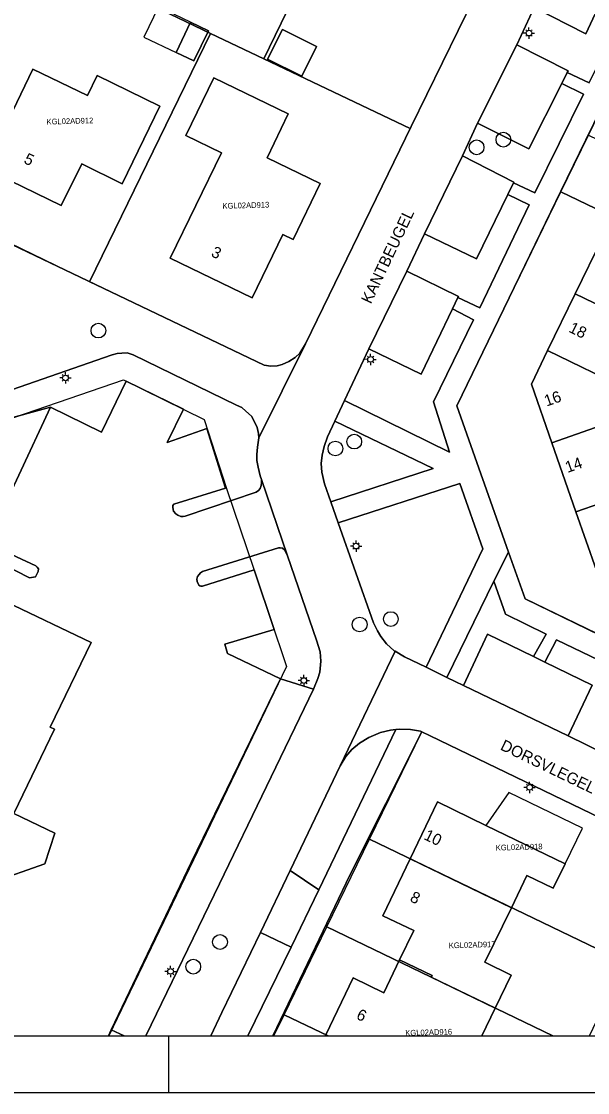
# Model space of a CAD drawing. Extents: x 124901 to 125496, y 515369 to 515789.
# Drawn here: x 125378 to 125427.9, y 515368.5 to 515463 of the extents above; entities that cross this region are included whole.
import ezdxf

# ---------------------------------------------------------------- set-up
doc = ezdxf.new("R2010")
doc.units = 0
for name, color, linetype in [('Alg Kaders', 7, 'Continuous'), ('Gebouw', 7, 'Continuous'), ('Inrit', 7, 'Continuous'), ('Lichtmast', 7, 'Continuous'), ('Luifel', 7, 'Continuous'), ('Onbegroeid terrein', 7, 'Continuous'), ('Parkeren', 7, 'Continuous'), ('Perceelnummers', 7, 'Continuous'), ('Perceelsgrenzen', 7, 'Continuous'), ('Putten', 7, 'Continuous'), ('Teksten', 7, 'Continuous'), ('Vegetatie', 7, 'Continuous'), ('Voetpad', 7, 'Continuous'), ('Wegen lokale weg', 7, 'Continuous')]:
    doc.layers.add(name, color=color, linetype=linetype)

msp = doc.modelspace()

# ---------------------------------------------------------------- linework, layer by layer
at = {"layer": 'Alg Kaders'}
msp.add_line((125390.924, 515373.543), (125390.926, 515368.543), dxfattribs=at)
for points in [[(125495.925, 515789.043), (124901.425, 515789.043), (124901.425, 515368.543), (125495.925, 515368.543)], [(125490.925, 515784.043), (124906.425, 515784.043), (124906.425, 515373.543), (125490.925, 515373.543)]]:
    msp.add_lwpolyline(points, close=True, dxfattribs=at)
at = {"layer": 'Gebouw'}
for points in [[(125391.586, 515460.272), (125393.165, 515459.518), (125394.441, 515462.189), (125392.862, 515462.943)], [(125400.963, 515462.304), (125399.651, 515459.678), (125402.66, 515458.174), (125403.972, 515460.801)], [(125384.62, 515458.25), (125383.768, 515456.476), (125378.95, 515458.79), (125374.731, 515450.024), (125381.47, 515446.78), (125383.268, 515450.44), (125386.83, 515448.69), (125390.16, 515455.54)], [(125398.293, 515438.629), (125400.999, 515444.211), (125401.898, 515443.775), (125404.29, 515448.71), (125399.606, 515450.977), (125401.48, 515454.85), (125394.91, 515458.03), (125392.448, 515452.952), (125395.585, 515451.431), (125391.076, 515442.128)], [(125429.2, 515443.99), (125426.768, 515438.975), (125434.939, 515435.036), (125437.359, 515440.057)], [(125431.364, 515430.569), (125432.54, 515430.06), (125434.939, 515435.036), (125426.768, 515438.975), (125424.342, 515433.974)], [(125431.364, 515430.569), (125424.342, 515433.974), (125422.91, 515431.02), (125424.711, 515425.853), (125431.246, 515428.13), (125430.757, 515429.488)], [(125431.246, 515428.13), (125424.711, 515425.853), (125426.84, 515419.745), (125433.44, 515422.046)], [(125431.621, 515413.142), (125435.027, 515420.2), (125433.911, 515420.74), (125433.44, 515422.046), (125426.84, 515419.745), (125428.64, 515414.58)], [(125414.63, 515394.17), (125412.224, 515389.156), (125421.143, 515384.841), (125422.519, 515387.686), (125424.837, 515386.564), (125425.88, 515388.72), (125418.886, 515392.108)], [(125412.224, 515389.156), (125409.817, 515384.142), (125412.537, 515382.837), (125411.288, 515380.235), (125414.154, 515378.859), (125414.086, 515378.718), (125419.721, 515375.991), (125421.134, 515378.911), (125418.816, 515380.032), (125421.143, 515384.841)]]:
    msp.add_lwpolyline(points, close=True, dxfattribs=at)
for points in [[(125372.005, 515373.543), (125369.392, 515381.106), (125374.299, 515382.802), (125374.757, 515381.475), (125375.06, 515381.58), (125374.601, 515382.911), (125376.54, 515383.58), (125375.324, 515387.078), (125380.02, 515388.71), (125380.89, 515391.42), (125377.294, 515393.154), (125380.88, 515400.59), (125380.493, 515400.777), (125384.09, 515408.22), (125376.623, 515411.811), (125376.81, 515412.2), (125374.711, 515413.213), (125369.39, 515415.78)], [(125418.537, 515373.543), (125419.721, 515375.991), (125414.086, 515378.718), (125414.154, 515378.859), (125411.288, 515380.235), (125409.903, 515377.35), (125407.184, 515378.655), (125404.78, 515373.646), (125404.992, 515373.543)], [(125404.992, 515373.543), (125404.78, 515373.646), (125404.731, 515373.543)]]:
    msp.add_lwpolyline(points, dxfattribs=at)
at = {"layer": 'Inrit'}
msp.add_lwpolyline([(125401.746, 515381.372), (125404.163, 515386.414), (125401.637, 515388.136), (125399.022, 515382.67)], close=True, dxfattribs=at)
at = {"layer": 'Lichtmast'}
for p, q in [((125422.396, 515461.981), (125422.196, 515461.98)), ((125422.484, 515462.192), (125422.414, 515462.263)), ((125422.696, 515462.28), (125422.696, 515462.48)), ((125422.908, 515462.192), (125422.979, 515462.264)), ((125422.996, 515461.98), (125423.196, 515461.98)), ((125422.484, 515461.768), (125422.412, 515461.697)), ((125422.696, 515461.68), (125422.696, 515461.48)), ((125422.908, 515461.768), (125422.978, 515461.697)), ((125408.52, 515433.418), (125408.45, 515433.489)), ((125408.732, 515433.506), (125408.732, 515433.706)), ((125408.944, 515433.418), (125409.015, 515433.49)), ((125408.432, 515433.207), (125408.232, 515433.206)), ((125408.52, 515432.994), (125408.448, 515432.923)), ((125408.732, 515432.906), (125408.732, 515432.706)), ((125408.944, 515432.994), (125409.014, 515432.923)), ((125409.032, 515433.206), (125409.232, 515433.206)), ((125381.622, 515431.776), (125381.552, 515431.847)), ((125381.834, 515431.864), (125381.834, 515432.064)), ((125382.046, 515431.776), (125382.117, 515431.848)), ((125381.534, 515431.565), (125381.334, 515431.564)), ((125381.622, 515431.352), (125381.55, 515431.281)), ((125381.834, 515431.264), (125381.834, 515431.064)), ((125382.046, 515431.352), (125382.116, 515431.281)), ((125382.134, 515431.564), (125382.334, 515431.564)), ((125407.157, 515416.737), (125406.957, 515416.736)), ((125407.245, 515416.524), (125407.173, 515416.453)), ((125407.245, 515416.948), (125407.175, 515417.019)), ((125407.457, 515417.036), (125407.457, 515417.236)), ((125407.669, 515416.948), (125407.74, 515417.02)), ((125407.669, 515416.524), (125407.739, 515416.453)), ((125407.757, 515416.736), (125407.957, 515416.736)), ((125407.457, 515416.436), (125407.457, 515416.236)), ((125402.632, 515405.09), (125402.562, 515405.161)), ((125402.844, 515405.178), (125402.844, 515405.378)), ((125403.056, 515405.09), (125403.127, 515405.162)), ((125402.544, 515404.879), (125402.344, 515404.878)), ((125402.632, 515404.666), (125402.56, 515404.595)), ((125402.844, 515404.578), (125402.844, 515404.378)), ((125403.056, 515404.666), (125403.126, 515404.595)), ((125403.144, 515404.878), (125403.344, 515404.878)), ((125422.544, 515395.671), (125422.474, 515395.742)), ((125422.756, 515395.759), (125422.756, 515395.959)), ((125422.968, 515395.671), (125423.039, 515395.743)), ((125422.456, 515395.46), (125422.256, 515395.459)), ((125422.544, 515395.247), (125422.472, 515395.176)), ((125422.756, 515395.159), (125422.756, 515394.959)), ((125422.968, 515395.247), (125423.038, 515395.176)), ((125423.056, 515395.459), (125423.256, 515395.459)), ((125391.1, 515379.532), (125391.1, 515379.732)), ((125390.8, 515379.233), (125390.6, 515379.232)), ((125390.888, 515379.02), (125390.816, 515378.949)), ((125390.888, 515379.444), (125390.818, 515379.515)), ((125391.1, 515378.932), (125391.1, 515378.732)), ((125391.312, 515379.444), (125391.383, 515379.516)), ((125391.312, 515379.02), (125391.382, 515378.949)), ((125391.4, 515379.232), (125391.6, 515379.232))]:
    msp.add_line(p, q, dxfattribs=at)
for centre in [(125422.696, 515461.98), (125408.732, 515433.206), (125381.834, 515431.564), (125407.457, 515416.736), (125402.844, 515404.878), (125422.756, 515395.459), (125391.1, 515379.232)]:
    msp.add_circle(centre, 0.25, dxfattribs=at)
at = {"layer": 'Luifel'}
for points in [[(125390.035, 515464.294), (125388.759, 515461.623), (125391.586, 515460.272), (125392.862, 515462.943)], [(125420.917, 515395.015), (125418.886, 515392.108), (125425.88, 515388.72), (125427.406, 515391.871)]]:
    msp.add_lwpolyline(points, close=True, dxfattribs=at)
at = {"layer": 'Onbegroeid terrein'}
for points in [[(125369.078, 515447.143), (125383.134, 515440.443), (125399.357, 515432.703), (125399.947, 515432.603), (125400.496, 515432.629), (125400.953, 515432.76), (125401.514, 515433.006), (125402.096, 515433.374), (125402.495, 515433.741), (125402.993, 515434.569), (125411.309, 515451.669), (125412.318, 515453.738), (125423.349, 515476.349), (125375.06, 515499.729)], [(125436.24, 515470.006), (125427.701, 515452.562), (125425.513, 515448.05), (125424.626, 515446.221), (125416.323, 515429.095), (125420.891, 515416.201), (125422.352, 515412.077), (125435.475, 515405.706)], [(125428.64, 515414.58), (125426.84, 515419.745), (125424.711, 515425.853), (125422.91, 515431.02), (125424.342, 515433.974), (125426.768, 515438.975), (125429.2, 515443.99)], [(125369.957, 515418.385), (125378.674, 515413.948), (125379.191, 515414.037), (125379.294, 515414.205), (125379.44, 515414.497), (125379.45, 515414.718), (125379.352, 515414.885), (125379.218, 515414.988), (125374.915, 515417.009), (125380.523, 515428.985), (125376.433, 515427.864)], [(125455.601, 515373.543), (125456.426, 515375.251), (125456.94, 515376.246), (125457.099, 515377.21), (125457.169, 515377.67), (125457.051, 515378.227), (125456.737, 515378.751), (125456.326, 515379.227), (125440.731, 515387.103), (125413.999, 515400.01), (125413.253, 515400.357), (125406.947, 515387.767), (125400.118, 515373.543)], [(125404.731, 515373.543), (125404.78, 515373.646), (125407.184, 515378.655), (125409.903, 515377.35), (125411.288, 515380.235), (125412.537, 515382.837), (125409.817, 515384.142), (125412.224, 515389.156), (125414.63, 515394.17), (125418.886, 515392.108), (125425.88, 515388.72), (125424.837, 515386.564), (125422.519, 515387.686), (125421.143, 515384.841), (125418.816, 515380.032), (125421.134, 515378.911), (125419.721, 515375.991), (125418.537, 515373.543)]]:
    msp.add_lwpolyline(points, dxfattribs=at)
for points in [[(125393.165, 515459.518), (125391.586, 515460.272), (125392.862, 515462.943), (125394.441, 515462.189)], [(125400.963, 515462.304), (125403.972, 515460.801), (125402.66, 515458.174), (125399.651, 515459.678)], [(125383.768, 515456.476), (125384.62, 515458.25), (125390.16, 515455.54), (125386.83, 515448.69), (125383.268, 515450.44), (125381.47, 515446.78), (125374.731, 515450.024), (125378.95, 515458.79)], [(125400.999, 515444.211), (125398.293, 515438.629), (125391.076, 515442.128), (125395.585, 515451.431), (125392.448, 515452.952), (125394.91, 515458.03), (125401.48, 515454.85), (125399.606, 515450.977), (125404.29, 515448.71), (125401.898, 515443.775)]]:
    msp.add_lwpolyline(points, close=True, dxfattribs=at)
at = {"layer": 'Parkeren'}
for points in [[(125430.901, 515468.821), (125426.393, 515471.074), (125423.161, 515464.229), (125427.7, 515461.925), (125430.399, 515467.739)], [(125425.582, 515457.541), (125426.06, 515458.488), (125426.14, 515458.647), (125421.631, 515460.932), (125418.166, 515454.044), (125422.673, 515451.779)], [(125413.485, 515444.285), (125418.062, 515442.058), (125420.827, 515447.752), (125421.319, 515448.766), (125421.355, 515448.839), (125416.83, 515451.144)], [(125416.434, 515438.648), (125416.484, 515438.751), (125411.918, 515440.973), (125408.592, 515434.124), (125413.18, 515431.909), (125415.962, 515437.669)], [(125426.147, 515400), (125428.263, 515404.477), (125424.088, 515406.504), (125423.096, 515406.986), (125419.029, 515408.959), (125416.917, 515404.45)]]:
    msp.add_lwpolyline(points, close=True, dxfattribs=at)
for points in [[(125385.618, 515373.543), (125385.878, 515374.087), (125392.925, 515388.832), (125400.783, 515405.027), (125396.109, 515407.269), (125395.894, 515408.083), (125400.241, 515409.387), (125398.458, 515414.653), (125393.917, 515413.214), (125393.758, 515413.21), (125393.672, 515413.233), (125393.592, 515413.292), (125393.435, 515413.601), (125393.408, 515413.834), (125393.463, 515414.057), (125393.614, 515414.227), (125393.741, 515414.382), (125393.905, 515414.501), (125400.603, 515416.584), (125400.754, 515416.57), (125400.981, 515416.544), (125401.186, 515416.391), (125401.421, 515415.89), (125399.132, 515422.604), (125399.12, 515422.305), (125399.088, 515422.071), (125398.989, 515421.829), (125398.863, 515421.638), (125398.651, 515421.488), (125392.398, 515419.377), (125392.212, 515419.341), (125392.001, 515419.355), (125391.742, 515419.462), (125391.567, 515419.58), (125391.367, 515419.808), (125391.305, 515420.13), (125391.305, 515420.31), (125391.395, 515420.436), (125395.958, 515421.837), (125394.288, 515427.106), (125390.812, 515425.885), (125392.249, 515428.807), (125387.195, 515431.286), (125385.023, 515426.793), (125380.523, 515428.985), (125374.915, 515417.009), (125379.218, 515414.988), (125379.352, 515414.885), (125379.45, 515414.718), (125379.44, 515414.497), (125379.294, 515414.205), (125379.191, 515414.037), (125378.674, 515413.948), (125369.957, 515418.385)], [(125376.623, 515411.811), (125384.09, 515408.22), (125380.493, 515400.777), (125380.88, 515400.59), (125377.294, 515393.154), (125380.89, 515391.42), (125380.02, 515388.71), (125375.324, 515387.078)]]:
    msp.add_lwpolyline(points, dxfattribs=at)
at = {"layer": 'Perceelsgrenzen'}
for points in [[(125375.06, 515499.729), (125385.193, 515494.823), (125397.791, 515488.723), (125410.427, 515482.605), (125423.349, 515476.349), (125412.23, 515453.557), (125411.309, 515451.669), (125402.993, 515434.569), (125402.495, 515433.741), (125402.096, 515433.374), (125401.514, 515433.006), (125400.953, 515432.76), (125400.496, 515432.629), (125399.947, 515432.603), (125399.357, 515432.703), (125383.955, 515440.045), (125372.915, 515445.397)], [(125347.273, 515373.543), (125347.035, 515373.992), (125346.605, 515374.956), (125346.243, 515375.947), (125345.95, 515376.96), (125337.56, 515398.86), (125339.28, 515400.59), (125345.594, 515417.203), (125386.949, 515431.401), (125394.052, 515427.9), (125396.029, 515421.819), (125398.444, 515414.714), (125401.327, 515406.13), (125385.649, 515373.543)], [(125345.594, 515417.203), (125386.949, 515431.401), (125394.052, 515427.9), (125396.029, 515421.819), (125398.444, 515414.714), (125401.327, 515406.13), (125385.649, 515373.543)], [(125400.202, 515373.543), (125401.109, 515375.407), (125404.88, 515383.155), (125408.641, 515390.882), (125413.253, 515400.357), (125413.999, 515400.01), (125435.675, 515389.544), (125440.731, 515387.103), (125456.326, 515379.227), (125456.737, 515378.751), (125457.051, 515378.227), (125457.169, 515377.67), (125457.099, 515377.21), (125456.94, 515376.246), (125456.426, 515375.251), (125455.601, 515373.543)], [(125424.786, 515373.543), (125404.88, 515383.155), (125408.641, 515390.882), (125431.133, 515380.048), (125428.337, 515374.2), (125428.285, 515374.092), (125428.015, 515373.543)], [(125404.984, 515373.543), (125401.109, 515375.407), (125404.88, 515383.155), (125424.786, 515373.543)], [(125400.202, 515373.543), (125401.109, 515375.407), (125404.984, 515373.543)]]:
    msp.add_lwpolyline(points, dxfattribs=at)
for points in [[(125394.62, 515461.95), (125386.705, 515465.759), (125397.791, 515488.723), (125410.427, 515482.605), (125399.333, 515459.704)], [(125410.427, 515482.605), (125423.349, 515476.349), (125412.23, 515453.557), (125399.333, 515459.704)], [(125394.62, 515461.95), (125383.955, 515440.045), (125372.915, 515445.397), (125370.542, 515452.147), (125370.68, 515452.487), (125378.816, 515469.556), (125386.705, 515465.759)], [(125422.352, 515412.077), (125416.323, 515429.095), (125425.515, 515447.977), (125427.947, 515452.971), (125430.307, 515457.819), (125432.68, 515462.693), (125436.24, 515470.006), (125458.379, 515459.386), (125466.196, 515455.636), (125473.945, 515451.919), (125481.696, 515448.201), (125490.418, 515444.017), (125486.87, 515436.73), (125484.12, 515431.04), (125477.96, 515418.22), (125473.069, 515420.579), (125472.365, 515419.12), (125460.158, 515393.807), (125453.949, 515396.807)], [(125394.62, 515461.95), (125399.333, 515459.704), (125412.23, 515453.557), (125411.309, 515451.669), (125402.993, 515434.569), (125402.495, 515433.741), (125402.096, 515433.374), (125401.514, 515433.006), (125400.953, 515432.76), (125400.496, 515432.629), (125399.947, 515432.603), (125399.357, 515432.703), (125383.955, 515440.045)], [(125425.515, 515447.977), (125427.947, 515452.971), (125450.152, 515442.29), (125447.75, 515437.274), (125430.08, 515445.77)], [(125453.949, 515396.807), (125422.352, 515412.077), (125416.323, 515429.095), (125425.515, 515447.977), (125430.08, 515445.77), (125447.75, 515437.274), (125449.679, 515436.346), (125447.917, 515432.714), (125453.762, 515429.894), (125461.501, 515426.16), (125469.259, 515422.417), (125473.069, 515420.579), (125472.365, 515419.12), (125466.225, 515422.082), (125465.264, 515420.091), (125461.584, 515412.672), (125460.064, 515409.52)], [(125431.133, 515380.048), (125408.641, 515390.882), (125413.253, 515400.357), (125413.999, 515400.01), (125435.675, 515389.544)]]:
    msp.add_lwpolyline(points, close=True, dxfattribs=at)
at = {"layer": 'Putten'}
for centre in [(125418.08, 515451.9), (125420.44, 515452.58), (125384.74, 515435.74), (125405.63, 515425.34), (125407.29, 515425.95), (125410.52, 515410.3), (125407.77, 515409.82), (125395.46, 515381.82), (125393.1, 515379.65)]:
    msp.add_circle(centre, 0.65, dxfattribs=at)
at = {"layer": 'Vegetatie'}
for points in [[(125421.631, 515460.932), (125426.14, 515458.647), (125426.06, 515458.488), (125428.014, 515457.588), (125432.457, 515466.767), (125430.399, 515467.739), (125427.7, 515461.925), (125423.161, 515464.229)], [(125425.582, 515457.541), (125422.673, 515451.779), (125418.166, 515454.044), (125416.83, 515451.144), (125421.355, 515448.839), (125421.319, 515448.766), (125423.219, 515447.878), (125427.49, 515456.592)], [(125420.827, 515447.752), (125418.062, 515442.058), (125413.485, 515444.285), (125411.918, 515440.973), (125416.484, 515438.751), (125416.434, 515438.648), (125418.36, 515437.737), (125422.705, 515446.846)], [(125415.962, 515437.669), (125413.18, 515431.909), (125408.592, 515434.124), (125406.432, 515429.562), (125415.691, 515425.014), (125414.289, 515429.452), (125417.805, 515436.694)], [(125404.628, 515425.529), (125404.453, 515424.746), (125404.384, 515424.022), (125404.436, 515423.262), (125404.66, 515422.237), (125405.221, 515420.648), (125414.265, 515423.583), (125405.575, 515427.751), (125404.926, 515426.381)], [(125410.89, 515407.472), (125411.714, 515406.97), (125413.621, 515406.046), (125418.625, 515416.487), (125416.601, 515422.265), (125405.875, 515418.797), (125408.998, 515409.957), (125409.353, 515409.254), (125409.624, 515408.777), (125410.144, 515408.114), (125410.82, 515407.514)], [(125400.783, 515405.027), (125403.713, 515404.119), (125404.079, 515405.064), (125404.253, 515405.631), (125404.34, 515406.575), (125404.28, 515407.423), (125403.978, 515408.446), (125401.421, 515415.89), (125401.186, 515416.391), (125400.981, 515416.544), (125400.754, 515416.57), (125400.603, 515416.584), (125393.905, 515414.501), (125393.741, 515414.382), (125393.614, 515414.227), (125393.463, 515414.057), (125393.408, 515413.834), (125393.435, 515413.601), (125393.592, 515413.292), (125393.672, 515413.233), (125393.758, 515413.21), (125393.917, 515413.214), (125398.458, 515414.653), (125400.241, 515409.387), (125395.894, 515408.083), (125396.109, 515407.269)], [(125419.029, 515408.959), (125423.096, 515406.986), (125424.199, 515408.973), (125420.617, 515410.742), (125419.603, 515413.638), (125415.465, 515405.153), (125416.917, 515404.45)], [(125428.263, 515404.477), (125426.147, 515400), (125431.103, 515397.551), (125433.34, 515402.034), (125437.38, 515400.095), (125438.393, 515402.078), (125425.11, 515408.481), (125424.088, 515406.504)], [(125407.072, 515398.8), (125406.548, 515398.168), (125406.048, 515397.354), (125401.637, 515388.136), (125404.163, 515386.414), (125410.945, 515400.557), (125410.484, 515400.502), (125409.616, 515400.303), (125408.567, 515399.848), (125407.742, 515399.356)]]:
    msp.add_lwpolyline(points, close=True, dxfattribs=at)
for points in [[(125376.433, 515427.864), (125380.523, 515428.985), (125385.023, 515426.793), (125387.195, 515431.286), (125392.249, 515428.807), (125390.812, 515425.885), (125394.288, 515427.106), (125395.958, 515421.837), (125391.395, 515420.436), (125391.305, 515420.31), (125391.305, 515420.13), (125391.367, 515419.808), (125391.567, 515419.58), (125391.742, 515419.462), (125392.001, 515419.355), (125392.212, 515419.341), (125392.398, 515419.377), (125398.651, 515421.488), (125398.863, 515421.638), (125398.989, 515421.829), (125399.088, 515422.071), (125399.12, 515422.305), (125399.132, 515422.604), (125399.012, 515422.941), (125398.812, 515423.705), (125398.711, 515424.294), (125398.702, 515424.828), (125398.766, 515425.453), (125398.882, 515426.281), (125398.849, 515426.667), (125398.729, 515427.184), (125398.537, 515427.642), (125398.223, 515428.181), (125397.751, 515428.65), (125397.373, 515428.945), (125396.919, 515429.164), (125387.816, 515433.589), (125387.261, 515433.791), (125386.8, 515433.752), (125386.398, 515433.725), (125385.959, 515433.617), (125375.706, 515430.042)], [(125388.934, 515373.543), (125395.406, 515386.94), (125403.713, 515404.119), (125400.783, 515405.027), (125392.925, 515388.832), (125385.878, 515374.087), (125387.016, 515373.543)], [(125397.907, 515373.543), (125401.746, 515381.372), (125399.022, 515382.67), (125395.635, 515375.592), (125394.645, 515373.543)], [(125387.016, 515373.543), (125385.878, 515374.087), (125385.618, 515373.543)]]:
    msp.add_lwpolyline(points, dxfattribs=at)
at = {"layer": 'Voetpad'}
for points in [[(125428.014, 515457.588), (125426.06, 515458.488), (125425.582, 515457.541), (125427.49, 515456.592), (125423.219, 515447.878), (125421.319, 515448.766), (125420.827, 515447.752), (125422.705, 515446.846), (125418.36, 515437.737), (125416.434, 515438.648), (125415.962, 515437.669), (125417.805, 515436.694), (125414.289, 515429.452), (125415.691, 515425.014), (125406.432, 515429.562), (125405.575, 515427.751), (125414.265, 515423.583), (125405.221, 515420.648), (125405.875, 515418.797), (125416.601, 515422.265), (125418.625, 515416.487), (125413.621, 515406.046), (125415.465, 515405.153), (125419.603, 515413.638), (125420.891, 515416.201), (125416.323, 515429.095), (125424.626, 515446.221), (125425.513, 515448.05), (125427.701, 515452.562), (125436.24, 515470.006)], [(125490.925, 515378.871), (125489.543, 515379.54), (125466.673, 515390.606), (125463.328, 515392.279), (125460.158, 515393.807), (125435.475, 515405.706), (125422.352, 515412.077), (125420.891, 515416.201), (125419.603, 515413.638), (125420.617, 515410.742), (125424.199, 515408.973), (125423.096, 515406.986), (125424.088, 515406.504), (125425.11, 515408.481), (125438.393, 515402.078), (125437.38, 515400.095), (125438.387, 515399.612), (125439.394, 515401.581), (125452.728, 515395.141), (125451.71, 515393.183), (125452.759, 515392.672), (125453.821, 515394.656), (125460.797, 515391.27), (125490.925, 515376.662)], [(125400.118, 515373.543), (125406.947, 515387.767), (125413.253, 515400.357), (125413.127, 515400.415), (125412.25, 515400.551), (125411.31, 515400.6), (125410.945, 515400.557), (125404.163, 515386.414), (125401.746, 515381.372), (125397.907, 515373.543)]]:
    msp.add_lwpolyline(points, dxfattribs=at)
at = {"layer": 'Wegen lokale weg'}
for points in [[(125423.349, 515476.349), (125412.318, 515453.738), (125411.309, 515451.669), (125402.993, 515434.569), (125398.882, 515426.281), (125398.766, 515425.453), (125398.702, 515424.828), (125398.711, 515424.294), (125398.812, 515423.705), (125399.012, 515422.941), (125399.132, 515422.604), (125401.421, 515415.89), (125403.978, 515408.446), (125404.28, 515407.423), (125404.34, 515406.575), (125404.253, 515405.631), (125404.079, 515405.064), (125403.713, 515404.119), (125395.406, 515386.94), (125388.934, 515373.543)], [(125394.645, 515373.543), (125395.635, 515375.592), (125399.022, 515382.67), (125401.637, 515388.136), (125406.048, 515397.354), (125410.89, 515407.472), (125410.82, 515407.514), (125410.144, 515408.114), (125409.624, 515408.777), (125409.353, 515409.254), (125408.998, 515409.957), (125405.875, 515418.797), (125405.221, 515420.648), (125404.66, 515422.237), (125404.436, 515423.262), (125404.384, 515424.022), (125404.453, 515424.746), (125404.628, 515425.529), (125404.926, 515426.381), (125405.575, 515427.751), (125406.432, 515429.562), (125408.592, 515434.124), (125411.918, 515440.973), (125413.485, 515444.285), (125416.83, 515451.144), (125418.166, 515454.044), (125421.631, 515460.932), (125423.161, 515464.229)], [(125375.706, 515430.042), (125385.959, 515433.617), (125386.398, 515433.725), (125386.8, 515433.752), (125387.261, 515433.791), (125387.816, 515433.589), (125396.919, 515429.164), (125397.373, 515428.945), (125397.751, 515428.65), (125398.223, 515428.181), (125398.537, 515427.642), (125398.729, 515427.184), (125398.849, 515426.667), (125398.882, 515426.281), (125402.993, 515434.569), (125402.495, 515433.741), (125402.096, 515433.374), (125401.514, 515433.006), (125400.953, 515432.76), (125400.496, 515432.629), (125399.947, 515432.603), (125399.357, 515432.703), (125383.134, 515440.443), (125369.078, 515447.143)], [(125431.103, 515397.551), (125426.147, 515400), (125416.917, 515404.45), (125415.465, 515405.153), (125413.621, 515406.046), (125411.714, 515406.97), (125410.89, 515407.472), (125406.048, 515397.354), (125406.548, 515398.168), (125407.072, 515398.8), (125407.742, 515399.356), (125408.567, 515399.848), (125409.616, 515400.303), (125410.484, 515400.502), (125410.945, 515400.557), (125411.31, 515400.6), (125412.25, 515400.551), (125413.127, 515400.415), (125413.253, 515400.357), (125413.999, 515400.01), (125440.731, 515387.103)]]:
    msp.add_lwpolyline(points, dxfattribs=at)

# ---------------------------------------------------------------- texts
at = {"layer": 'Perceelnummers'}
for s, rotation, p in [('KGL02AD912', 1.6343, (125380.172, 515453.909)), ('KGL02AD913', 1.63448, (125395.684, 515446.482)), ('KGL02AD918', 1.63476, (125419.773, 515389.884)), ('KGL02AD917', 1.63471, (125415.633, 515381.264)), ('KGL02AD916', 1.63467, (125411.799, 515373.551))]:
    msp.add_text(s, height=0.5, rotation=rotation, dxfattribs=at).set_placement(p)
at = {"layer": 'Teksten'}
for s, rotation, p in [('5', 334.3, (125378.087, 515450.552)), ('KANTBEUGEL', 64.6, (125408.756, 515438.034)), ('3', 334.1, (125394.599, 515442.336)), ('18', 334.1, (125426.129, 515435.658)), ('16', 19.2, (125424.239, 515429.036)), ('14', 19.2, (125426.092, 515423.183)), ('DORSVLEGEL', 334.2, (125420.099, 515398.819)), ('10', 334.4, (125413.356, 515390.909)), ('8', 334.4, (125412.132, 515385.449)), ('6', 334.4, (125407.401, 515375.084))]:
    msp.add_text(s, height=1, rotation=rotation, dxfattribs=at).set_placement(p)

doc.saveas('drawing.dxf')
